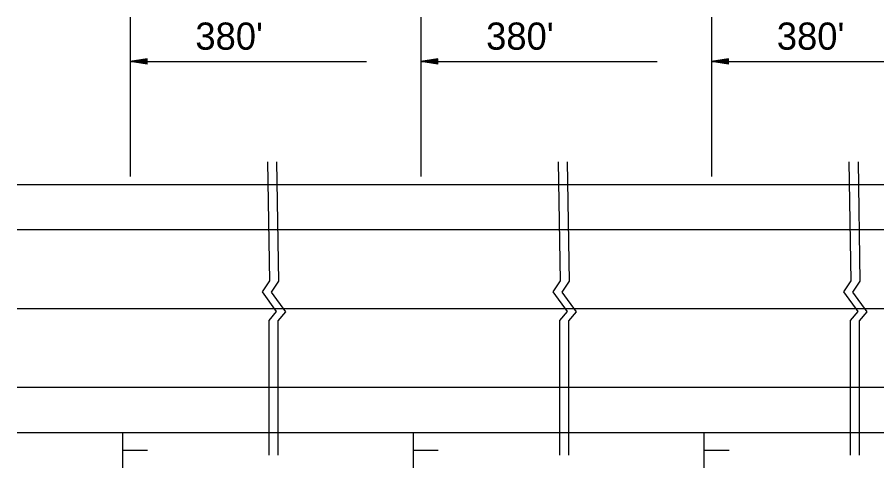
# Model space of a CAD drawing. Extents: x 1678017 to 1687792, y 404433 to 413488.
# Drawn here: x 1678938.65 to 1678957.62, y 409293.16 to 409303.11 of the extents above; entities that cross this region are included whole.
import ezdxf

# ---------------------------------------------------------------- set-up
doc = ezdxf.new("R2010")
doc.units = 0
doc.layers.add('Default', color=7, linetype='Continuous')

msp = doc.modelspace()

# ---------------------------------------------------------------- linework, layer by layer
at = {"layer": 'Default'}
for p, q in [((1678941.139, 409303.107), (1678941.139, 409299.586)), ((1678947.555, 409303.107), (1678947.555, 409299.586)), ((1678953.971, 409303.107), (1678953.971, 409299.586)), ((1678941.514, 409302.184), (1678941.139, 409302.128)), ((1678941.514, 409302.175), (1678941.202, 409302.128)), ((1678941.514, 409302.165), (1678941.266, 409302.128)), ((1678941.514, 409302.156), (1678941.329, 409302.128)), ((1678941.514, 409302.147), (1678941.392, 409302.128)), ((1678941.514, 409302.137), (1678941.455, 409302.128)), ((1678941.514, 409302.072), (1678941.514, 409302.184)), ((1678947.93, 409302.184), (1678947.555, 409302.128)), ((1678947.93, 409302.175), (1678947.618, 409302.128)), ((1678947.93, 409302.165), (1678947.683, 409302.128)), ((1678947.93, 409302.156), (1678947.745, 409302.128)), ((1678947.93, 409302.147), (1678947.809, 409302.128)), ((1678947.93, 409302.137), (1678947.871, 409302.128)), ((1678947.93, 409302.072), (1678947.93, 409302.184)), ((1678954.346, 409302.184), (1678953.971, 409302.128)), ((1678954.346, 409302.175), (1678954.034, 409302.128)), ((1678954.346, 409302.165), (1678954.099, 409302.128)), ((1678954.346, 409302.156), (1678954.161, 409302.128)), ((1678954.346, 409302.147), (1678954.225, 409302.128)), ((1678954.346, 409302.137), (1678954.287, 409302.128)), ((1678954.346, 409302.072), (1678954.346, 409302.184)), ((1678941.139, 409302.128), (1678946.358, 409302.128)), ((1678941.514, 409302.072), (1678941.139, 409302.128)), ((1678941.514, 409302.081), (1678941.202, 409302.128)), ((1678941.514, 409302.091), (1678941.266, 409302.128)), ((1678941.514, 409302.1), (1678941.329, 409302.128)), ((1678941.514, 409302.11), (1678941.392, 409302.128)), ((1678941.514, 409302.119), (1678941.455, 409302.128)), ((1678947.555, 409302.128), (1678952.774, 409302.128)), ((1678947.93, 409302.072), (1678947.555, 409302.128)), ((1678947.93, 409302.081), (1678947.618, 409302.128)), ((1678947.93, 409302.091), (1678947.683, 409302.128)), ((1678947.93, 409302.1), (1678947.745, 409302.128)), ((1678947.93, 409302.11), (1678947.809, 409302.128)), ((1678947.93, 409302.119), (1678947.871, 409302.128)), ((1678953.971, 409302.128), (1678959.19, 409302.128)), ((1678954.346, 409302.072), (1678953.971, 409302.128)), ((1678954.346, 409302.081), (1678954.034, 409302.128)), ((1678954.346, 409302.091), (1678954.099, 409302.128)), ((1678954.346, 409302.1), (1678954.161, 409302.128)), ((1678954.346, 409302.11), (1678954.225, 409302.128)), ((1678954.346, 409302.119), (1678954.287, 409302.128)), ((1678938.648, 409299.416), (1679044.482, 409299.416)), ((1678938.648, 409298.416), (1678993.524, 409298.416)), ((1678938.648, 409296.678), (1678982.279, 409296.678)), ((1678938.648, 409294.939), (1678993.524, 409294.939)), ((1678938.648, 409293.939), (1679044.482, 409293.939)), ((1678940.981, 409293.157), (1678940.981, 409293.939)), ((1678947.397, 409293.157), (1678947.397, 409293.939)), ((1678953.813, 409293.157), (1678953.813, 409293.939)), ((1678940.992, 409293.546), (1678941.526, 409293.546)), ((1678947.408, 409293.546), (1678947.942, 409293.546)), ((1678953.824, 409293.546), (1678954.358, 409293.546))]:
    msp.add_line(p, q, dxfattribs=at)
for points in [[(1678944.173, 409299.916), (1678944.213, 409297.284), (1678944.051, 409297.042), (1678944.367, 409296.609), (1678944.2, 409296.409), (1678944.2, 409293.439)], [(1678944.373, 409299.916), (1678944.413, 409297.275), (1678944.25, 409297.034), (1678944.567, 409296.601), (1678944.4, 409296.401), (1678944.4, 409293.439)], [(1678950.589, 409299.916), (1678950.629, 409297.284), (1678950.467, 409297.042), (1678950.783, 409296.609), (1678950.617, 409296.409), (1678950.616, 409293.439)], [(1678950.789, 409299.916), (1678950.829, 409297.275), (1678950.666, 409297.034), (1678950.983, 409296.601), (1678950.816, 409296.401), (1678950.816, 409293.439)], [(1678957.005, 409299.916), (1678957.045, 409297.284), (1678956.883, 409297.042), (1678957.199, 409296.609), (1678957.033, 409296.409), (1678957.032, 409293.439)], [(1678957.205, 409299.916), (1678957.245, 409297.275), (1678957.083, 409297.034), (1678957.399, 409296.601), (1678957.232, 409296.401), (1678957.232, 409293.439)]]:
    msp.add_lwpolyline(points, dxfattribs=at)

# ---------------------------------------------------------------- texts
for p in [(1678942.58, 409302.389), (1678948.997, 409302.389), (1678955.413, 409302.389)]:
    msp.add_text("380'", height=0.6, dxfattribs=at).set_placement(p)

doc.saveas('drawing.dxf')
